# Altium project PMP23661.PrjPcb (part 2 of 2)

## Sheet PMP23661_Secondary Drivers.SchDoc
size 431 x 279 mm; Date: Not shown in title block; ApprovedBy: Not shown in title block; CheckedBy: Not shown in title block; Author: Not shown in title block; CompanyName: Not shown in title block; Engineer: Not shown in title block; Organization: Not shown in title block; Address1: Not shown in title block; Address2: Not shown in title block; Address3: Not shown in title block; Address4: Not shown in title block; DocumentNumber: 3; Revision: Use project parameter SCH_Rev; SheetNumber: 3; SheetTotal: 3; PageSetup: Record=PageOptions¦CenterHorizontal=True¦CenterVertical=True¦PrintScale=1.00¦XCorrection=1.00¦YCorrection=1.00¦PrintKind=0¦BorderSize=5000000¦LeftOffset=0¦BottomOffset=0¦Orientation=2¦PaperLength=1000¦PaperWidth=1000¦Scale=100¦PaperSource=15¦PrintQuality=600¦MediaType=1¦DitherType=10¦PaperKind=Letter¦PrintScaleMode=1
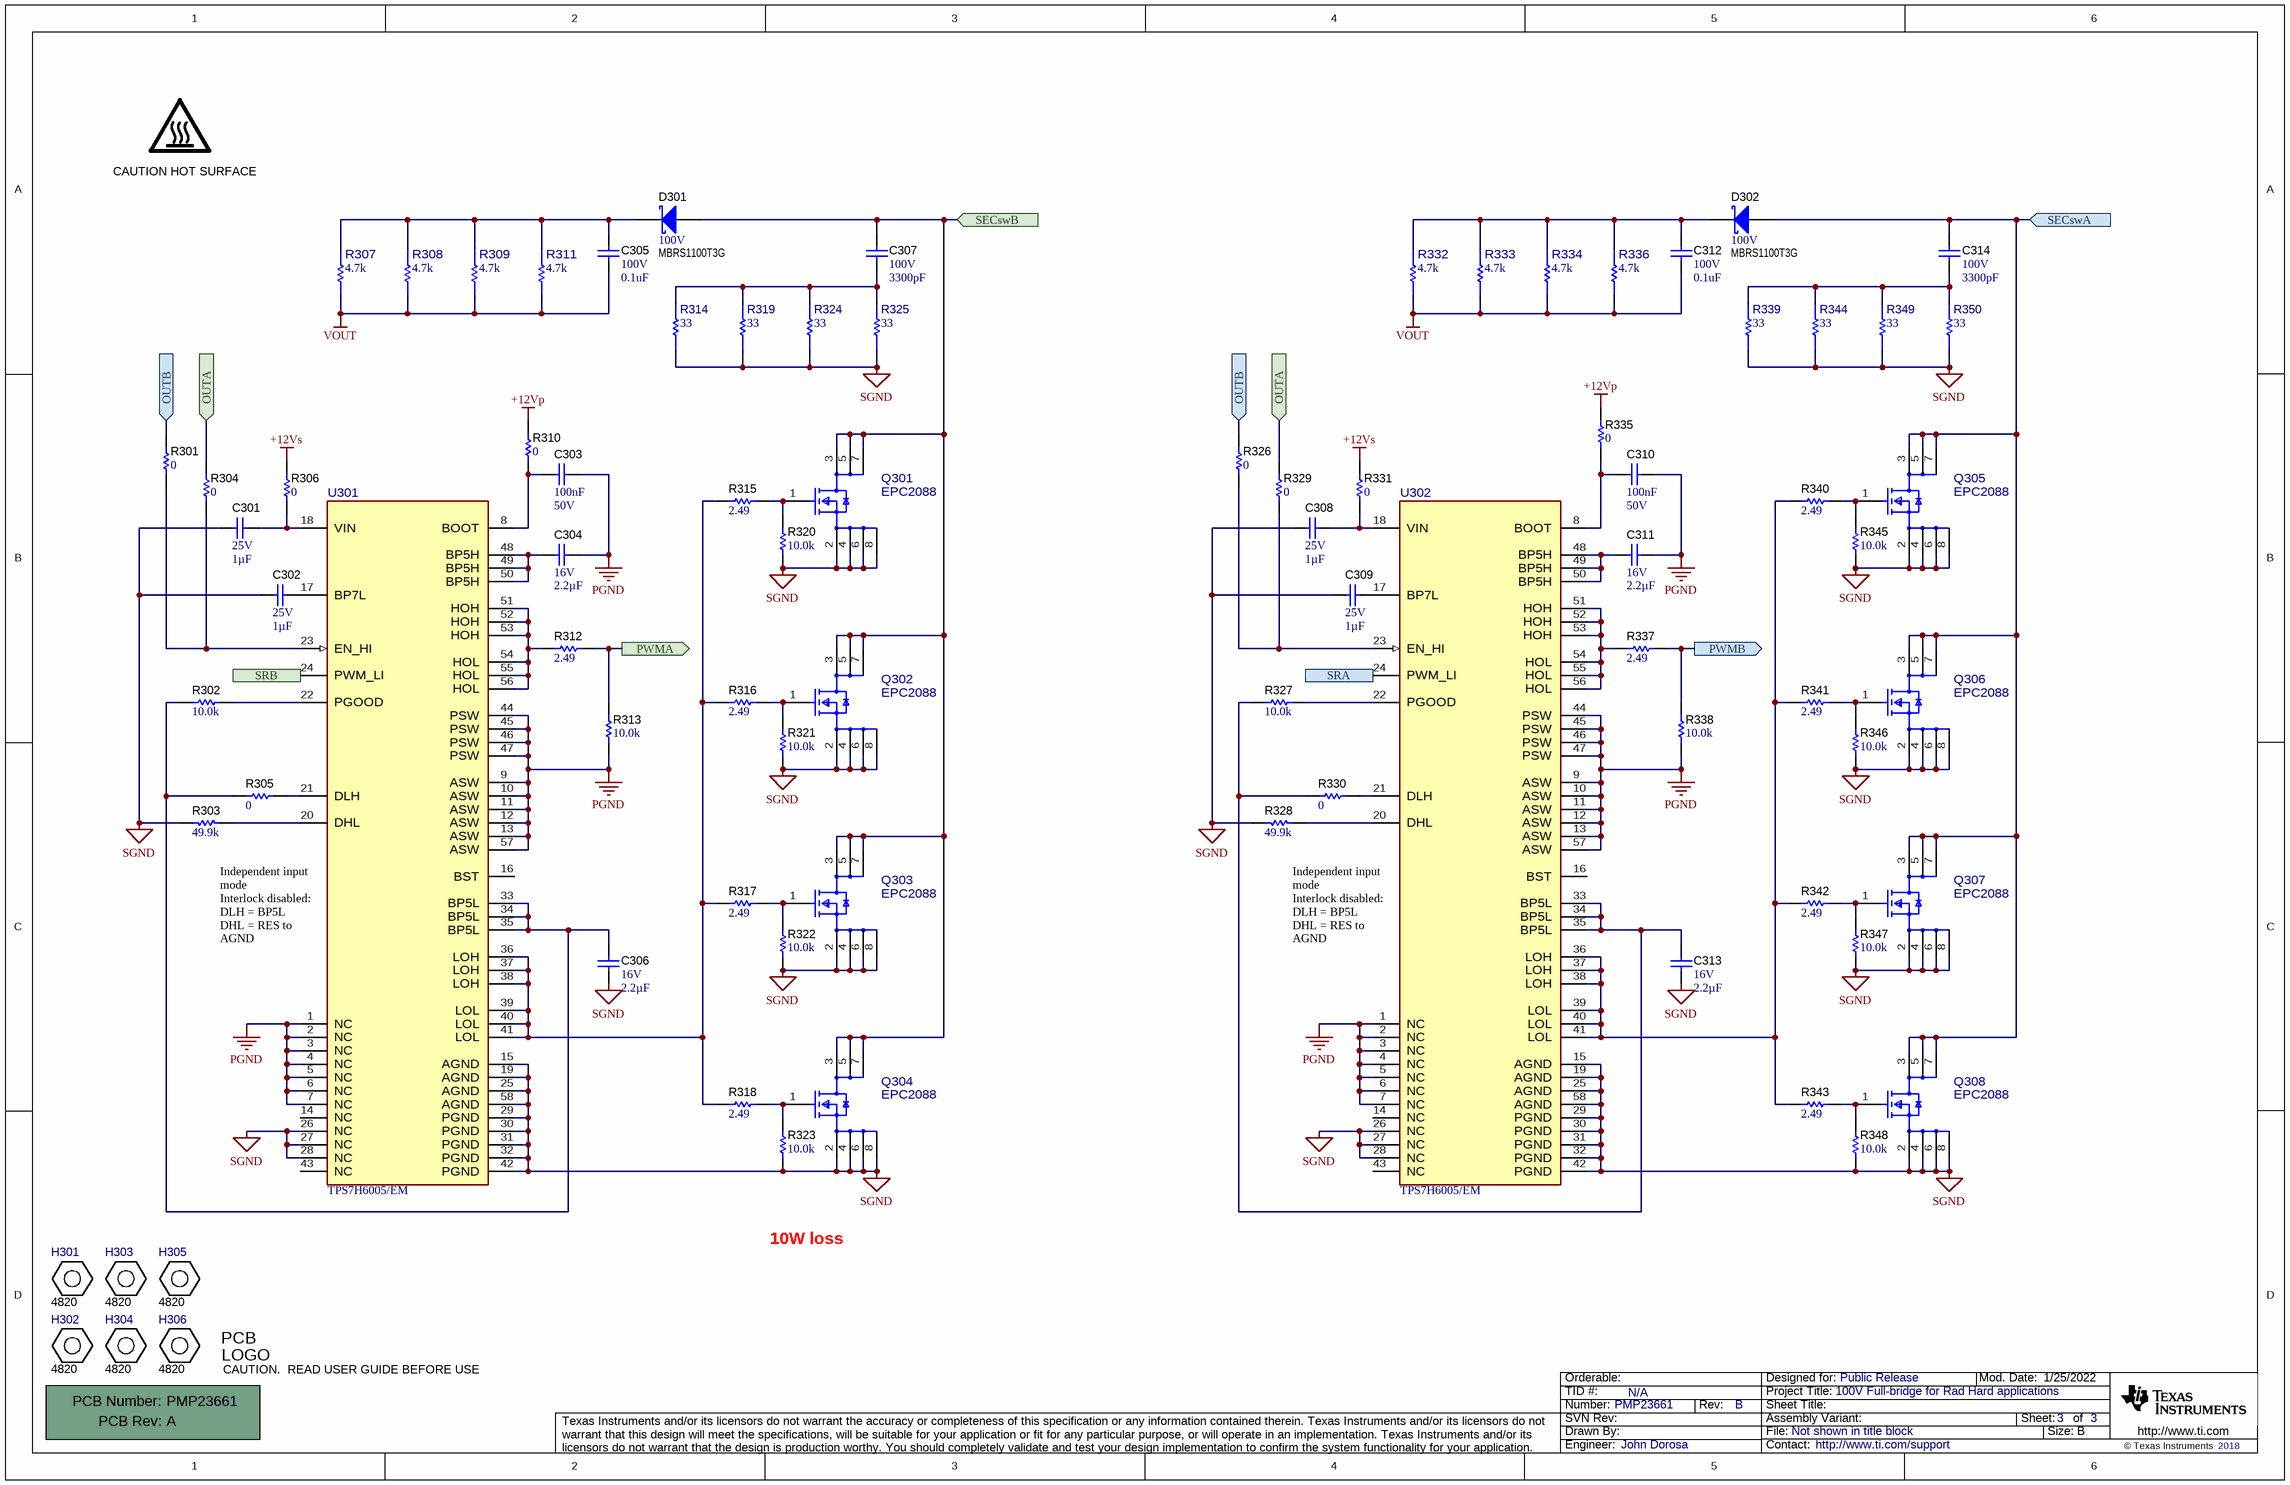
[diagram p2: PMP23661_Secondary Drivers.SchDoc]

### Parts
!PCB301  Printed Circuit Board  (value not drawn)  (mechanical)
C301  VDC_V: 25V  Cap_F: 1µF  [0603_HV]  (hidden comment: GRM188R71E105KA12D)
C302  VDC_V: 25V  Cap_F: 1µF  [0603_HV]  (hidden comment: GRM188R71E105KA12D)
C303  Cap_F: 100nF  VDC_V: 50V  [0603_HV]  (hidden comment: C0603C104K5RACAUTO)
C304  VDC_V: 16V  Cap_F: 2.2µF  [0603_HV]  (hidden comment: GRM188Z71C225KE43)
C305  VDC_V: 100V  ValueDisplayed: 0.1uF  [1206]  (hidden comment: GRM319R72A104KA01D)
C306  VDC_V: 16V  Cap_F: 2.2µF  [0603_HV]  (hidden comment: GRM188Z71C225KE43)
C307  VDC_V: 100V  ValueDisplayed: 3300pF  [1206]  (hidden comment: 12061C332KAT2A)
C308  VDC_V: 25V  Cap_F: 1µF  [0603_HV]  (hidden comment: GRM188R71E105KA12D)
C309  VDC_V: 25V  Cap_F: 1µF  [0603_HV]  (hidden comment: GRM188R71E105KA12D)
C310  Cap_F: 100nF  VDC_V: 50V  [0603_HV]  (hidden comment: C0603C104K5RACAUTO)
C311  VDC_V: 16V  Cap_F: 2.2µF  [0603_HV]  (hidden comment: GRM188Z71C225KE43)
C312  VDC_V: 100V  ValueDisplayed: 0.1uF  [1206]  (hidden comment: GRM319R72A104KA01D)
C313  VDC_V: 16V  Cap_F: 2.2µF  [0603_HV]  (hidden comment: GRM188Z71C225KE43)
C314  VDC_V: 100V  ValueDisplayed: 3300pF  [1206]  (hidden comment: 12061C332KAT2A)
D301  MBRS1100T3G  value 100V  [SMB]
D302  MBRS1100T3G  value 100V  [SMB]
H301  4820  [KEYSTONE_4820]
H302  4820  [KEYSTONE_4820]
H303  4820  [KEYSTONE_4820]
H304  4820  [KEYSTONE_4820]
H305  4820  [KEYSTONE_4820]
H306  4820  [KEYSTONE_4820]
Logo301  CAUTION HOT SURFACE  [IEC_HotSurface_Medium]  (no BOM)
Logo302  CAUTION.  READ USER GUIDE BEFORE USE  [IEC_Caution_Small]  (no BOM)
Q301  EPC2088  [FP-EPC2088_LGA8-MFG]
Q302  EPC2088  [FP-EPC2088_LGA8-MFG]
Q303  EPC2088  [FP-EPC2088_LGA8-MFG]
Q304  EPC2088  [FP-EPC2088_LGA8-MFG]
Q305  EPC2088  [FP-EPC2088_LGA8-MFG]
Q306  EPC2088  [FP-EPC2088_LGA8-MFG]
Q307  EPC2088  [FP-EPC2088_LGA8-MFG]
Q308  EPC2088  [FP-EPC2088_LGA8-MFG]
R301  ValueDisplayed: 0  [0603_HV]  (hidden comment: CRCW06030000Z0EA)
R302  ValueDisplayed: 10.0k  [0603_HV]  (hidden comment: CRCW060310K0FKEA)
R303  ValueDisplayed: 49.9k  [0603_HV]  (hidden comment: CRCW060349K9FKEA)
R304  ValueDisplayed: 0  [0603_HV]  (hidden comment: CRCW06030000Z0EA)
R305  ValueDisplayed: 0  [0603_HV]  (hidden comment: CRCW06030000Z0EA)
R306  ValueDisplayed: 0  [0603_HV]  (hidden comment: CRCW06030000Z0EA)
R307  value 4.7k  [FP-CRGP2512F4K7_2512-IPC_C]  (hidden comment: CRGP2512F4K7)
R308  value 4.7k  [FP-CRGP2512F4K7_2512-IPC_C]  (hidden comment: CRGP2512F4K7)
R309  value 4.7k  [FP-CRGP2512F4K7_2512-IPC_C]  (hidden comment: CRGP2512F4K7)
R310  ValueDisplayed: 0  [0603_HV]  (hidden comment: CRCW06030000Z0EA)
R311  value 4.7k  [FP-CRGP2512F4K7_2512-IPC_C]  (hidden comment: CRGP2512F4K7)
R312  ValueDisplayed: 2.49  [0603_HV]  (hidden comment: CRCW06032R49FKEA)
R313  ValueDisplayed: 10.0k  [0603_HV]  (hidden comment: CRCW060310K0FKEA)
R314  value 33  [FP-3522330KFT_2512-IPC_A]  (hidden comment: 352233RJT)
R315  ValueDisplayed: 2.49  [0603_HV]  (hidden comment: CRCW06032R49FKEA)
R316  ValueDisplayed: 2.49  [0603_HV]  (hidden comment: CRCW06032R49FKEA)
R317  ValueDisplayed: 2.49  [0603_HV]  (hidden comment: CRCW06032R49FKEA)
R318  ValueDisplayed: 2.49  [0603_HV]  (hidden comment: CRCW06032R49FKEA)
R319  value 33  [FP-3522330KFT_2512-IPC_A]  (hidden comment: 352233RJT)
R320  ValueDisplayed: 10.0k  [0603_HV]  (hidden comment: CRCW060310K0FKEA)
R321  ValueDisplayed: 10.0k  [0603_HV]  (hidden comment: CRCW060310K0FKEA)
R322  ValueDisplayed: 10.0k  [0603_HV]  (hidden comment: CRCW060310K0FKEA)
R323  ValueDisplayed: 10.0k  [0603_HV]  (hidden comment: CRCW060310K0FKEA)
R324  value 33  [FP-3522330KFT_2512-IPC_A]  (hidden comment: 352233RJT)
R325  value 33  [FP-3522330KFT_2512-IPC_A]  (hidden comment: 352233RJT)
R326  ValueDisplayed: 0  [0603_HV]  (hidden comment: CRCW06030000Z0EA)
R327  ValueDisplayed: 10.0k  [0603_HV]  (hidden comment: CRCW060310K0FKEA)
R328  ValueDisplayed: 49.9k  [0603_HV]  (hidden comment: CRCW060349K9FKEA)
R329  ValueDisplayed: 0  [0603_HV]  (hidden comment: CRCW06030000Z0EA)
R330  ValueDisplayed: 0  [0603_HV]  (hidden comment: CRCW06030000Z0EA)
R331  ValueDisplayed: 0  [0603_HV]  (hidden comment: CRCW06030000Z0EA)
R332  value 4.7k  [FP-CRGP2512F4K7_2512-IPC_C]  (hidden comment: CRGP2512F4K7)
R333  value 4.7k  [FP-CRGP2512F4K7_2512-IPC_C]  (hidden comment: CRGP2512F4K7)
R334  value 4.7k  [FP-CRGP2512F4K7_2512-IPC_C]  (hidden comment: CRGP2512F4K7)
R335  ValueDisplayed: 0  [0603_HV]  (hidden comment: CRCW06030000Z0EA)
R336  value 4.7k  [FP-CRGP2512F4K7_2512-IPC_C]  (hidden comment: CRGP2512F4K7)
R337  ValueDisplayed: 2.49  [0603_HV]  (hidden comment: CRCW06032R49FKEA)
R338  ValueDisplayed: 10.0k  [0603_HV]  (hidden comment: CRCW060310K0FKEA)
R339  value 33  [FP-3522330KFT_2512-IPC_A]  (hidden comment: 352233RJT)
R340  ValueDisplayed: 2.49  [0603_HV]  (hidden comment: CRCW06032R49FKEA)
R341  ValueDisplayed: 2.49  [0603_HV]  (hidden comment: CRCW06032R49FKEA)
R342  ValueDisplayed: 2.49  [0603_HV]  (hidden comment: CRCW06032R49FKEA)
R343  ValueDisplayed: 2.49  [0603_HV]  (hidden comment: CRCW06032R49FKEA)
R344  value 33  [FP-3522330KFT_2512-IPC_A]  (hidden comment: 352233RJT)
R345  ValueDisplayed: 10.0k  [0603_HV]  (hidden comment: CRCW060310K0FKEA)
R346  ValueDisplayed: 10.0k  [0603_HV]  (hidden comment: CRCW060310K0FKEA)
R347  ValueDisplayed: 10.0k  [0603_HV]  (hidden comment: CRCW060310K0FKEA)
R348  ValueDisplayed: 10.0k  [0603_HV]  (hidden comment: CRCW060310K0FKEA)
R349  value 33  [FP-3522330KFT_2512-IPC_A]  (hidden comment: 352233RJT)
R350  value 33  [FP-3522330KFT_2512-IPC_A]  (hidden comment: 352233RJT)
U301  TPS7H6005/EM  [DCA0056M-MFG]
U302  TPS7H6005/EM  [DCA0056M-MFG]

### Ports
OUTA (in), OUTB (in), PWMA (out), PWMB (out), SECswA (in), SECswB (in), SRA (in), SRB (in)

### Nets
+12Vp: R310.1 R335.1
+12Vs: R306.1 R331.1
PGND: C303.1 C304.1 C310.1 C311.1 R313.2 R338.2 U301.1(NC) U301.2(NC) U301.3(NC) U301.4(NC) U301.5(NC) U301.6(NC) U301.7(NC) U301.9(ASW) U301.10(ASW) U301.11(ASW) U301.12(ASW) U301.13(ASW) U301.44(PSW) U301.45(PSW) U301.46(PSW) U301.47(PSW) U301.57(ASW) U302.1(NC) U302.2(NC) U302.3(NC) U302.4(NC) U302.5(NC) U302.6(NC) U302.7(NC) U302.9(ASW) U302.10(ASW) U302.11(ASW) U302.12(ASW) U302.13(ASW) U302.44(PSW) U302.45(PSW) U302.46(PSW) U302.47(PSW) U302.57(ASW)
SGND: C301.2 C302.1 C306.1 C308.2 C309.1 C313.1 Q301.2(Source) Q301.4(Source) Q301.6(Source) Q301.8(Source) Q302.2(Source) Q302.4(Source) Q302.6(Source) Q302.8(Source) Q303.2(Source) Q303.4(Source) Q303.6(Source) Q303.8(Source) Q304.2(Source) Q304.4(Source) Q304.6(Source) Q304.8(Source) Q305.2(Source) Q305.4(Source) Q305.6(Source) Q305.8(Source) Q306.2(Source) Q306.4(Source) Q306.6(Source) Q306.8(Source) Q307.2(Source) Q307.4(Source) Q307.6(Source) Q307.8(Source) Q308.2(Source) Q308.4(Source) Q308.6(Source) Q308.8(Source) R303.2 R314.1 R319.1 R320.2 R321.2 R322.2 R323.2 R324.1 R325.1 R328.2 R339.1 R344.1 R345.2 R346.2 R347.2 R348.2 R349.1 R350.1 U301.15(AGND) U301.19(AGND) U301.25(AGND) U301.26(NC) U301.27(NC) U301.28(NC) U301.29(PGND) U301.30(PGND) U301.31(PGND) U301.32(PGND) U301.42(PGND) U301.58(AGND) U302.15(AGND) U302.19(AGND) U302.25(AGND) U302.26(NC) U302.27(NC) U302.28(NC) U302.29(PGND) U302.30(PGND) U302.31(PGND) U302.32(PGND) U302.42(PGND) U302.58(AGND)
VOUT: C305.2 C312.2 R307.2 R308.2 R309.2 R311.2 R332.2 R333.2 R334.2 R336.2
OUTA: R304.1 R329.1 ; port OUTA
OUTB: R301.1 R326.1 ; port OUTB
PWMA: R312.1 R313.1 ; port PWMA
PWMB: R337.1 R338.1 ; port PWMB
SECswA: C314.1 D302.2(A) Q305.3(Drain) Q305.5(Drain) Q305.7(Drain) Q306.3(Drain) Q306.5(Drain) Q306.7(Drain) Q307.3(Drain) Q307.5(Drain) Q307.7(Drain) Q308.3(Drain) Q308.5(Drain) Q308.7(Drain) ; port SECswA
SECswB: C307.1 D301.2(A) Q301.3(Drain) Q301.5(Drain) Q301.7(Drain) Q302.3(Drain) Q302.5(Drain) Q302.7(Drain) Q303.3(Drain) Q303.5(Drain) Q303.7(Drain) Q304.3(Drain) Q304.5(Drain) Q304.7(Drain) ; port SECswB
SRA: U302.24(PWM_LI) ; port SRA
SRB: U301.24(PWM_LI) ; port SRB
NetC301_1: C301.1 R306.2 U301.18(VIN)
NetC302_2: C302.2 U301.17(BP7L)
NetC303_2: C303.2 R310.2 U301.8(BOOT)
NetC304_2: C304.2 U301.48(BP5H) U301.49(BP5H) U301.50(BP5H)
NetC305_1: C305.1 D301.1(K) R307.1 R308.1 R309.1 R311.1
NetC306_2: C306.2 R302.2 R305.1 U301.33(BP5L) U301.34(BP5L) U301.35(BP5L)
NetC307_2: C307.2 R314.2 R319.2 R324.2 R325.2
NetC308_1: C308.1 R331.2 U302.18(VIN)
NetC309_2: C309.2 U302.17(BP7L)
NetC310_2: C310.2 R335.2 U302.8(BOOT)
NetC311_2: C311.2 U302.48(BP5H) U302.49(BP5H) U302.50(BP5H)
NetC312_1: C312.1 D302.1(K) R332.1 R333.1 R334.1 R336.1
NetC313_2: C313.2 R327.2 R330.1 U302.33(BP5L) U302.34(BP5L) U302.35(BP5L)
NetC314_2: C314.2 R339.2 R344.2 R349.2 R350.2
NetQ301_1: Q301.1(Gate) R315.1 R320.1
NetQ302_1: Q302.1(Gate) R316.1 R321.1
NetQ303_1: Q303.1(Gate) R317.1 R322.1
NetQ304_1: Q304.1(Gate) R318.1 R323.1
NetQ305_1: Q305.1(Gate) R340.1 R345.1
NetQ306_1: Q306.1(Gate) R341.1 R346.1
NetQ307_1: Q307.1(Gate) R342.1 R347.1
NetQ308_1: Q308.1(Gate) R343.1 R348.1
NetR301_2: R301.2 R304.2 U301.23(EN_HI)
NetR302_1: R302.1 U301.22(PGOOD)
NetR303_1: R303.1 U301.20(DHL)
NetR305_2: R305.2 U301.21(DLH)
NetR312_2: R312.2 U301.51(HOH) U301.52(HOH) U301.53(HOH) U301.54(HOL) U301.55(HOL) U301.56(HOL)
NetR315_2: R315.2 R316.2 R317.2 R318.2 U301.36(LOH) U301.37(LOH) U301.38(LOH) U301.39(LOL) U301.40(LOL) U301.41(LOL)
NetR326_2: R326.2 R329.2 U302.23(EN_HI)
NetR327_1: R327.1 U302.22(PGOOD)
NetR328_1: R328.1 U302.20(DHL)
NetR330_2: R330.2 U302.21(DLH)
NetR337_2: R337.2 U302.51(HOH) U302.52(HOH) U302.53(HOH) U302.54(HOL) U302.55(HOL) U302.56(HOL)
NetR340_2: R340.2 R341.2 R342.2 R343.2 U302.36(LOH) U302.37(LOH) U302.38(LOH) U302.39(LOL) U302.40(LOL) U302.41(LOL)

Not connected (* = marked no-connect by the designer): U301 14(NC) 16(BST) 43(NC); U302 14(NC) 16(BST) 43(NC)

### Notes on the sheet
- (near U301) Independent input mode
  Interlock disabled:
  DLH = BP5L
  DHL = RES to AGND
- (near U302) Independent input mode
  Interlock disabled:
  DLH = BP5L
  DHL = RES to AGND
- 10W loss

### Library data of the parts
!PCB301 = CMP-0003618-2: Manufacturer: Any; PartNumber: PMP23661
C301 C302 C308 C309 = CMP-0007405-5: CAP, CERM, 1 uF, 25 V, +/- 10%, X7R, 0603; Manufacturer: MuRata; Cap_Case: 0603; AEC Category: Q200; Value: 1uF; SizeX_mm: 1.6; U/M: EA; Value1: Unknown; SizeAreaWB_mm2: 4.68; SizeY_mm: 0.8; TaMin_C: -55°C; SizeZ_mm: 1; Polarized: N; MFG_Status: TI_Obsolete; TaMax_C: 125°C; SizeArea_mm2: 1.28
C303 C310 = CMP-0079602-1: CAP, CERM, 0.1 µF, 50 V,+/- 10%, X7R, AEC-Q200 Grade 1, 0603; Manufacturer: Kemet; TaMin_C: -55°C; Polarized: N; SizeAreaWB_mm2: 4.68; U/M: EA; Value: 0.1uF; TaMax_C: 125°C; SizeZ_mm: 1; SizeX_mm: 1.6; SizeY_mm: 0.8; Cap_Case: 0603; SizeArea_mm2: 1.28; AEC Qualified: Y; AEC Category: Q200; ValueDisplayed: 0.1µF
C304 C306 C311 C313 = CMP-0007499-4: CAP, CERM, 2.2 uF, 16 V, +/- 10%, X7R, 0603; Manufacturer: MuRata; TaMin_C: -55°C; Polarized: N; SizeAreaWB_mm2: 4.68; Value1: Unknown; U/M: EA; Value: 2.2uF; TaMax_C: 125°C; SizeZ_mm: 1; SizeX_mm: 1.6; SizeY_mm: 0.8; Cap_Case: 0603; SizeArea_mm2: 1.28; AEC Category: Q200
C305 C312 = CMP-0008881-2: CAP, CERM, 0.1 uF, 100 V, +/- 10%, X7R, 1206; Manufacturer: MuRata; TaMin_C: -55°C; Polarized: N; SizeAreaWB_mm2: 10.92; Value1: Unknown; U/M: EA; Value: 0.1uF; TaMax_C: 125°C; SizeZ_mm: 1.35; SizeX_mm: 3.2; SizeY_mm: 1.6; SizeArea_mm2: 5.12; Cap_F: 100nF; AEC Category: Q200
C307 C314 = CMP-0008497-2: CAP, CERM, 3300 pF, 100 V, +/- 10%, X7R, 1206; Manufacturer: AVX; TaMin_C: -55°C; ESR_ohm: 0.216; Polarized: N; SizeAreaWB_mm2: 10.92; Value1: 0.216 ohm; U/M: EA; Value: 3300pF; TaMax_C: 125°C; SizeZ_mm: 1.35; SizeX_mm: 3.2; SizeY_mm: 1.6; SizeArea_mm2: 5.12; Cap_F: 3.3nF; AEC Category: Q200
D301 D302 = CMP-0028521-2: Diode, Schottky, 100 V, 1 A, SMB; Manufacturer: ON Semiconductor; TJmax_C: 150°C; SizeY_mm: 3.81; RJC_CperW: 22; Value1: 1A; SizeAreaWB_mm2: 44.156; Green_Lifecycle: Active; SizeArea_mm2: 21.336; Vf_V: 750mV; SizeZ_mm: 2.6; SizeX_mm: 5.6; Green_REACh: Passed; Value2: 0.75V; AEC Category: Q101
H301-H306 = CMP-0003652-1: Manufacturer: Keystone; CompType: Standoff
Logo301 = CMP-0074837-2: IEC 61010-1 Hot Surface Warning; Manufacturer: Texas Instruments; CompType: IC; AEC Category: Q200; SymbolCreator: a0412235
Logo302 = CMP-0074836-1: IEC 61010-1 Caution Warning; SymbolCreator: a0412235; Lib Reference: IEC_Caution
Q301-Q308 = CMP-0122030-1: N-Channel 100 V 60A (Ta) Surface Mount Die; Manufacturer: EPC; AEC Qualified: No; QgTyp_nC: 12.5nC @ 5V; Rdson45_ohm: 2.4m; SizeZ_mm: 0.675mm; VdsMax_V: 100V; Vgs_V: 6V; ChMode: False; Input Capacitace At Vds: 1864pF @ 50V; Number Of Channels: 1; Pulse Drain Current: 231A; Rthja Max: 53°C/W; Standoff Height: 0.108mm; Threshold Vgs Max: 2.5V; Threshold Vgs Min: 0.7V; TJmax_C: +150°C; Typ Forward Diode Voltage: 1.5V
R301 R304-R306 R310 R326 R329-R331 R335 = CMP-0025697-4: RES, 0, 5%, 0.1 W, AEC-Q200 Grade 0, 0603; Manufacturer: Vishay-Dale; Power_W: 100mW; TempCo: 200 ppm/C; Value_Code: 0000; Value: 0; EIA_Code: E24; SizeX_mm: 1.6; SizeY_mm: 0.8; SizeZ_mm: 1; Value2: 0.1W; SizeArea_mm2: 1.28; AEC Qualified: Y; VDC_V: 75V; AEC Category: Q200
R302 R313 R320-R323 R327 R338 R345-R348 = CMP-0021998-4: RES, 10.0 k, 1%, 0.1 W, AEC-Q200 Grade 0, 0603; Manufacturer: Vishay-Dale; Power_W: 100mW; TempCo: 100 ppm/C; Value_Code: 10k0; Value: 10.0k; EIA_Code: E96; Res_ohm: 10k; SizeX_mm: 1.6; SizeY_mm: 0.8; SizeZ_mm: 1; Value2: 0.1W; SizeArea_mm2: 1.28; AEC Qualified: Y; VDC_V: 75V; AEC Category: Q200; AEC Grade: 0
R303 R328 = CMP-0022447-4: RES, 49.9 k, 1%, 0.1 W, AEC-Q200 Grade 0, 0603; Manufacturer: Vishay-Dale; Power_W: 100mW; TempCo: 100 ppm/C; Value_Code: 49k9; Value: 49.9k; EIA_Code: E96; SizeX_mm: 1.6; SizeY_mm: 0.8; SizeZ_mm: 1; Value2: 0.1W; SizeArea_mm2: 1.28; AEC Qualified: Y; VDC_V: 75V; AEC Category: Q200; AEC Grade: 0
R307-R309 R311 R332-R334 R336 = CMP-0126315-1: Res Thick Film 2512 4.7K Ohm 1% 2W ±100ppm/C Pad SMD T/R Automotive AEC-Q200; Manufacturer: TE; AEC Grade: Grade 0; AEC Qualified: Yes; SizeZ_mm: 0.65mm; TempCo: 100ppm/°C; VDC_V: 500V; TaMax_C: +70°C
R312 R315-R318 R337 R340-R343 = CMP-0022311-4: RES, 2.49, 1%, 0.1 W, AEC-Q200 Grade 0, 0603; Manufacturer: Vishay-Dale; Power_W: 100mW; TempCo: 100 ppm/C; Value_Code: 2R49; Value: 2.49; EIA_Code: E96; SizeX_mm: 1.6; SizeY_mm: 0.8; SizeZ_mm: 1; Value2: 0.1W; SizeArea_mm2: 1.28; AEC Qualified: Y; VDC_V: 75V; AEC Category: Q200; AEC Grade: 0
R314 R319 R324 R325 R339 R344 R349 R350 = CMP-0096995-1: Res Thick Film 2512 33 Ohm 1% 3W ±100ppm/C Pad SMD Automotive T/R; Manufacturer: TE Connectivity; VDC_V: 250V; TempCo: 100ppm/°C; AEC Qualified: Yes; SizeZ_mm: 1.2mm; AEC Grade: Grade 0; Res_ohm: 330k
U301 U302 = CMP-0120202-4: Manufacturer: Texas Instruments; SizeZ_mm: 1.2mm; Standoff Height: 0.05mm; AEC Category: Q200; CompType: IC

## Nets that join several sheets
+12Vp: PMP23661_Controller (J102.5), PMP23661_Primary Drivers (J201.1 J205.1 R202.1 R213.1), PMP23661_Secondary Drivers (R310.1 R335.1)
+12Vs: PMP23661_Controller (J103.1 R101.2 R105.1), PMP23661_Secondary Drivers (R306.1 R331.1)
PGND: PMP23661_Controller (14 pins), PMP23661_Primary Drivers (56 pins), PMP23661_Secondary Drivers (40 pins)
SGND: PMP23661_Controller (55 pins), PMP23661_Secondary Drivers (80 pins)
VOUT: PMP23661_Controller (23 pins), PMP23661_Secondary Drivers (10 pins)
OUTA: PMP23661_Controller (R109.2 R119.2 U101.10), PMP23661_Secondary Drivers (R304.1 R329.1)
OUTB: PMP23661_Controller (R110.2 R118.2 U101.11), PMP23661_Secondary Drivers (R301.1 R326.1)
PRIswA: PMP23661_Controller (D105.2 D106.1 L101.1 T102.1), PMP23661_Primary Drivers (30 pins)
PRIswB: PMP23661_Controller (D107.2 D108.1 T103.2), PMP23661_Primary Drivers (30 pins)
PWMA: PMP23661_Primary Drivers (J205.3 R212.2), PMP23661_Secondary Drivers (R312.1 R313.1)
PWMB: PMP23661_Primary Drivers (J201.3 R201.2), PMP23661_Secondary Drivers (R337.1 R338.1)
SECswA: PMP23661_Controller (D113.1 L102.1 T103.3), PMP23661_Secondary Drivers (14 pins)
SECswB: PMP23661_Controller (D114.1 L103.2 T103.4), PMP23661_Secondary Drivers (14 pins)
SRA: PMP23661_Controller (U101.15), PMP23661_Secondary Drivers (U302.24)
SRB: PMP23661_Controller (U101.14), PMP23661_Secondary Drivers (U301.24)
VIN: PMP23661_Controller (5 pins), PMP23661_Primary Drivers (12 pins)

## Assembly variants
001: not fitted D109 D110 D111 D112 H301 H302 H303 H304 H305 H306 J201 J202 J203 J204 J205 J206 J207 J208 Q101 Q102 R106 R109 R110 R112 R113 R114 R115 R116 R118 R119 R120 R122 R125 R301 R329 T102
